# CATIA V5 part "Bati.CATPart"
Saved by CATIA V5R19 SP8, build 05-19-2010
Part number: Bati
Bounding box of the stored display mesh (mm): x -15 to 105, y -60 to 60, z -11 to 12.5
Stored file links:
  G:\EU_thinkMotion\CFAO_2010\MMS_groupe1\MMS_groupe1\A reprendre\OK\glenerrant\glenerrant\glenerrant\Bati.CATPart
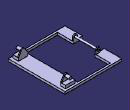
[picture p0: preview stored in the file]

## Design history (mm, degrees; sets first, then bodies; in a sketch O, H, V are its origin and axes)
Set1
  Point1: (0, -23, 0)
  Point2: (0, 23, 0)
  Point3: (89, -51, 8)
  Point4: (89, 51, 8)
  Point5: (0, 0, 0)
  Plane1: type Offset, RefPlane zx-plane, Offset 23
  Plane2: type Offset, RefPlane zx-plane, Offset 23, reversed
Body1 (main body)
  Sketch1 on zx-plane, origin (0, 0, 0), H (-1, 0, 0), V (0, 0, 1)
    circle A1 centre (0, 0) radius 2
    point P1 (0, 0)
    reference projected point E1 (0, 0) from Point5
    radius A1 = 2
    coincidence: P1 E1
  Pad1: profile Sketch1, direction (0, 1, 0), length 26, opposite side length 26
  Sketch2 on Plane2, origin (0, -23, 0), H (-1, 0, 0), V (0, 0, 1)
    circle A1 centre (0, 0) radius 2
    point P1 (0, 0)
    circle A2 centre (0, 0) radius 4.6268
    point P2 (0, 0)
    reference projected point E1 (0, 0) from Point1
    reference projected point E2 (0, 0) from Point1
    radius A2 = 4.6268
    radius A1 = 2
    coincidence: E1 P1, P2 E2
  Pad2: profile Sketch2, direction (0, -1, 0), length 2
  Sketch3 on Plane1, origin (0, 23, 0), H (-1, 0, 0), V (0, 0, 1)
    circle A1 centre (0, 0) radius 4.5
    point P1 (0, 0)
    circle A2 centre (0, 0) radius 2
    point P2 (0, 0)
    reference projected point E1 (0, 0) from Point2
    reference projected point E2 (0, 0) from Point2
    radius A2 = 2
    radius A1 = 4.5
    coincidence: P2 E1, P1 E2
  Pad3: profile Sketch3, direction (0, 1, 0), length 2
  Sketch4 on Plane2, origin (0, -23, 0), H (-1, 0, 0), V (0, 0, 1)
    line L1 (-4.5, 0) -> (-4.5, -6)
    point P1 (-4.5, 0)
    line L2 (4.5, 0) -> (4.5, -6)
    point P3 (4.5, 0)
    line L3 (-4.5, -6) -> (4.5, -6)
    arc A1 centre (0, 0) radius 4.5 from (-4.5, 0) to (4.5, 0) ccw
    point P5 (0, 0)
    reference projected point E1 (0, 0) from Point5
    reference projected point E2 (0, 0) from Point5
    point P6 (-4.5, 0)
    point P7 (4.5, 0)
    radius A1 = 4.5
    distance E2 L3 = 6
    vertical: L1 V, L2 V
    horizontal: L3 H
    coincidence: P5 E1, P3 A1, P1 A1, L2 P7, L1 P6
    tangency: L2 A1, L1 A1
  Pad4: profile Sketch4, direction (0, -1, 0), length 2
  Sketch5 on Plane1, origin (0, 23, 0), H (-1, 0, 0), V (0, 0, 1)
    point P1 (-4.5, 0)
    point P2 (4.5, 0)
    arc A1 centre (0, 0) radius 4.5 from (-4.5, 0) to (4.5, 0) ccw
    point P3 (0, 0)
    reference projected point E1 (0, 0) from Point5
    line L1 (4.5, 0) -> (4.5, -6)
    point P4 (4.5, 0)
    line L2 (4.5, -6) -> (-4.5, -6)
    line L3 (-4.5, -6) -> (-4.5, 0)
    point P7 (-4.5, 0)
    point P8 (-4.5, 0)
    point P9 (4.5, 0)
    reference projected point E2 (0, 0) from Point5
    radius A1 = 4.5
    distance E2 L2 = 6
    coincidence: E1 P3, P4 A1, P7 A1, L1 P9, L3 P8
    vertical: L1 V, L3 V
    horizontal: L2 H
    tangency: A1 L3, L1 A1
  Pad5: profile Sketch5, direction (0, 1, 0), length 2
  Plane3: stored without definition
  Sketch6 on face of Pad5 from Sketch5.L2, origin (0, 0, -6), H (1, 0, 0), V (0, -1, 0)
    line L1 (-15, 60) -> (105, 60)
    line L2 (105, 60) -> (105, -60)
    line L3 (105, -60) -> (-15, -60)
    line L4 (-15, -60) -> (-15, -23)
    reference projected point E1 (0, 0) from Point5
    reference projected point E2 (0, 0) from Point5
    line L5 (5, 56) -> (75, 56)
    line L6 (75, 56) -> (75, -56)
    line L7 (75, -56) -> (5, -56)
    line L8 (5, -56) -> (5, -23)
    point P9 (-15, 23)
    line L9 (-15, 23) -> (5, 23)
    line L10 (5, -23) -> (-15, -23)
    reference projected line E3 (4.5, 23) -> (-4.5, 23) from edge [face of Pad4 from Sketch4.L3 | start face of Pad4]
    reference projected line E4 (4.5, -23) -> (-4.5, -23) from edge [start face of Pad5 | face of Pad5 from Sketch5.L2]
    line L11 (5, 23) -> (5, 56)
    line L12 (-15, 23) -> (-15, 60)
    length L2 = 120
    length L1 = 120
    distance E1 L4 = 15
    distance E2 L3 = 60
    length L5 = 70
    distance L6 L2 = 30
    distance L7 L3 = 4
    distance L5 L1 = 4
    horizontal: L1 H, L3 H, L5 H, L7 H, L9 H, L10 H
    vertical: L2 V, L4 V, L6 V, L8 V, L11 V, L12 V
    coincidence: P9 L4, E3 L9, L10 E4, L8 L11, L4 L12
  Pad6: profile Sketch6, direction (0, 0, -1), length 5
  Sketch7 on Plane3, origin (0, -46.5, 0), H (-1, 0, 0), V (0, 0, 1)
    circle A1 centre (-89, 8) radius 4.5
    point P1 (-89, 8)
    reference projected point E1 (-89, 8) from Point3
    radius A1 = 4.5
    coincidence: E1 P1
  Pad7: profile Sketch7, direction (0, 1, 0), length 2
  Plane4: stored without definition
  Sketch8 on Plane3, origin (0, -46.5, 0), H (-1, 0, 0), V (0, 0, 1)
    circle A1 centre (-89, 8) radius 3
    point P1 (-89, 8)
    reference projected point E1 (-89, 8) from Point3
    radius A1 = 3
    coincidence: E1 P1
  Pad8: profile Sketch8, direction (0, -1, 0), length 10
  Sketch9 on Plane4, origin (0, 46.5, 0), H (-1, 0, 0), V (0, 0, 1)
    circle A1 centre (-89, 8) radius 4.5
    point P1 (-89, 8)
    reference projected point E1 (-89, 8) from Point4
    radius A1 = 4.5
    coincidence: P1 E1
  Pad9: profile Sketch9, direction (0, -1, 0), length 2
  Sketch10 on Plane4, origin (0, 46.5, 0), H (-1, 0, 0), V (0, 0, 1)
    circle A1 centre (-89, 8) radius 3
    point P1 (-89, 8)
    reference projected point E1 (-89, 8) from Point4
    radius A1 = 3
    coincidence: E1 P1
  Pad10: profile Sketch10, direction (0, 1, 0), length 9
  Sketch11 on Plane4, origin (0, 46.5, 0), H (-1, 0, 0), V (0, 0, 1)
    line L1 (-92.8361, 10.3526) -> (-99.185, 0)
    point P2 (-99.185, 0)
    line L2 (-85.1029, 10.25) -> (-79.185, 0)
    point P4 (-79.185, 0)
    line L3 (-99.185, 0) -> (-79.185, 0)
    point P5 (-99.185, 0)
    point P6 (-79.185, 0)
    arc A1 centre (-89, 8) radius 4.5 from (-92.8361, 10.3526) to (-85.1029, 10.25) ccw
    point P7 (-89, 8)
    reference projected point E1 (-89, 8) from Point4
    reference projected point E2 (-89, 8) from Point4
    reference intersected line E3 through (0, 0) direction (-1, 0) from xy-plane
    radius A1 = 4.5
    distance L3 E2 = 8
    length L3 = 20
    angle L2 L3 = 60
    coincidence: P7 E1, P6 P4, P2 P5
    tangency: L1 A1, A1 L2
    parallelism: E3 L3
  Pad11: profile Sketch11, direction (0, -1, 0), length 2
  Sketch12 on Plane3, origin (0, -46.5, 0), H (-1, 0, 0), V (0, 0, 1)
    arc A1 centre (-89, 8) radius 4.5 from (-92.8971, 10.25) to (-85.1639, 10.3526) ccw
    point P1 (-89, 8)
    reference projected point E1 (-89, 8) from Point4
    line L1 (-92.8971, 10.25) -> (-98.815, 0)
    point P3 (-98.815, 0)
    line L2 (-98.815, 0) -> (-78.815, 0)
    point P4 (-98.815, 0)
    line L3 (-78.815, 0) -> (-85.1639, 10.3526)
    reference intersected line E2 through (0, 0) direction (-1, 0) from xy-plane
    reference projected point E3 (-89, 8) from Point4
    radius A1 = 4.5
    length L2 = 20
    angle L1 L2 = 60
    distance E3 L2 = 8
    coincidence: P1 E1, P3 P4
    parallelism: E2 L2
    tangency: L3 A1, L1 A1
  Pad12: profile Sketch12, direction (0, 1, 0), length 2
  Sketch13 on face of Pad12 from Sketch12.L2, origin (0, 0, 0), H (1, 0, 0), V (0, -1, 0)
    line L1 (98.815, 56.5) -> (78.815, 56.5)
    line L2 (78.815, 56.5) -> (78.815, 44.5)
    line L3 (78.815, 44.5) -> (98.815, 44.5)
    line L4 (98.815, 44.5) -> (98.815, 56.5)
    reference projected line E1 (98.815, 46.5) -> (98.815, 44.5) from edge [face of Pad12 from Sketch12.L2 | face of Pad12 from Sketch12.L1]
    reference projected line E2 (98.815, 46.5) -> (98.815, 44.5) from edge [face of Pad12 from Sketch12.L2 | face of Pad12 from Sketch12.L1]
    reference projected line E3 (98.815, 46.5) -> (78.815, 46.5) from edge [start face of Pad12 | face of Pad12 from Sketch12.L2]
    reference projected line E4 (98.815, 44.5) -> (78.815, 44.5) from edge [face of Pad12 from Sketch12.L2 | end face of Pad12]
    length L3 = 20
    length L4 = 12
    horizontal: L1 H, L3 H
    vertical: L2 V, L4 V
    parallelism: L4 E1, L1 E3
    coincidence: L4 E2, L3 E4
  Pad13: profile Sketch13, direction (0, 0, -1), length 6
  Sketch14 on face of Pad11 from Sketch11.L3, origin (0, 0, 0), H (1, 0, 0), V (0, -1, 0)
    line L1 (99.185, -44.5) -> (79.185, -44.5)
    line L2 (79.185, -44.5) -> (79.185, -55.5)
    line L3 (79.185, -55.5) -> (99.185, -55.5)
    line L4 (99.185, -55.5) -> (99.185, -44.5)
    reference projected line E1 (99.185, -44.5) -> (79.185, -44.5) from edge [end face of Pad11 | face of Pad11 from Sketch11.L3]
    reference projected line E2 (99.185, -44.5) -> (79.185, -44.5) from edge [end face of Pad11 | face of Pad11 from Sketch11.L3]
    reference projected line E3 (99.185, -46.5) -> (99.185, -44.5) from edge [face of Pad11 from Sketch11.L1 | face of Pad11 from Sketch11.L3]
    reference projected line E4 (99.185, -46.5) -> (99.185, -44.5) from edge [face of Pad11 from Sketch11.L1 | face of Pad11 from Sketch11.L3]
    length L3 = 20
    length L4 = 11
    horizontal: L1 H, L3 H
    vertical: L2 V, L4 V
    coincidence: L1 E1, L4 E3
    parallelism: L1 E2, L4 E4
  Pad14: profile Sketch14, direction (0, 0, -1), length 6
